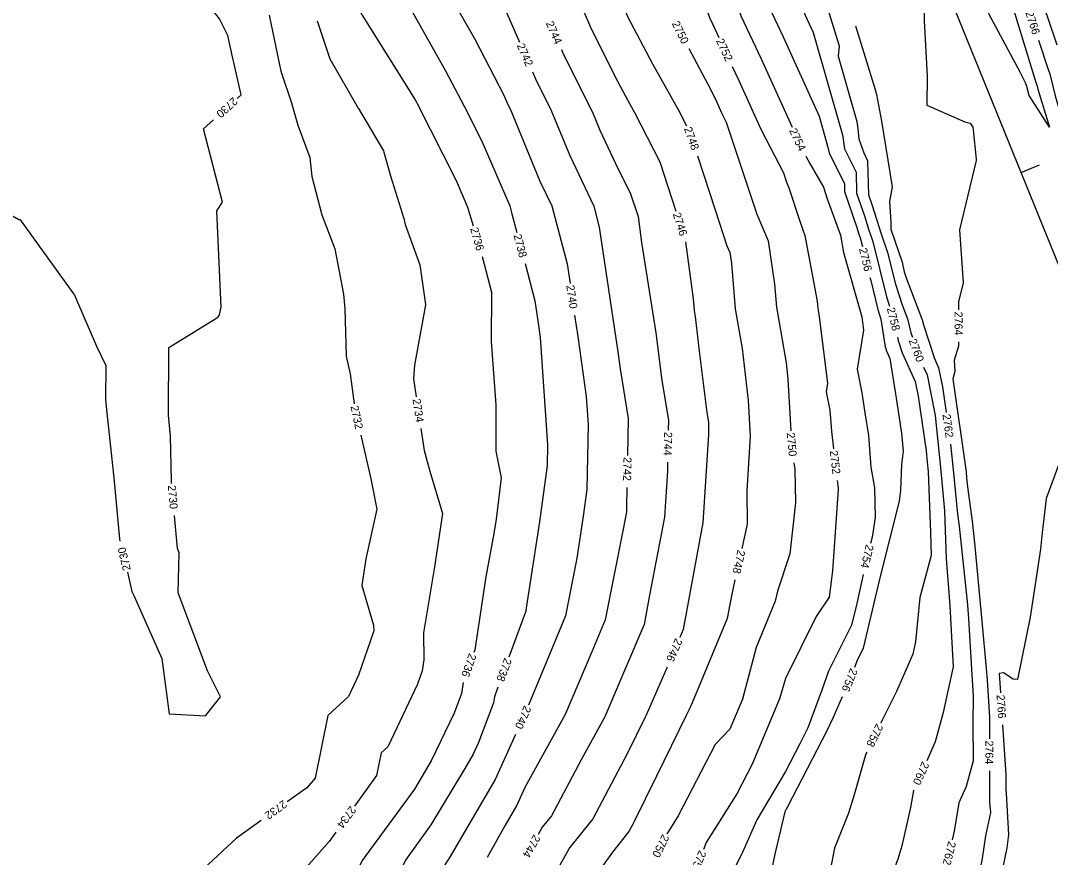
# Model space of a CAD drawing. Extents: x 1326424 to 1329294, y 1001359 to 1003823.
# Drawn here: x 1327991.3 to 1328248.6, y 1002477.9 to 1002687.1 of the extents above; entities that cross this region are included whole.
import ezdxf

# ---------------------------------------------------------------- set-up
doc = ezdxf.new("R2010")
doc.units = 0
for name, color, linetype in [('Prop RDY Alternate Text Yellow', 7, 'Continuous'), ('Prop Rem of Exist Asph Pvmt', 7, 'Continuous'), ('Prop SS Fill Line', 7, 'Continuous'), ('Scratch_Level_3', 7, 'Continuous')]:
    doc.layers.add(name, color=color, linetype=linetype)

msp = doc.modelspace()

# ---------------------------------------------------------------- linework, layer by layer
at = {"layer": 'Prop RDY Alternate Text Yellow'}
msp.add_line((1328073.66, 1003062.05), (1328254.1, 1002617.56), dxfattribs=at)
at = {"layer": 'Prop Rem of Exist Asph Pvmt'}
for points in [[(1328089.78, 1002713.03), (1328096.09, 1002698.14), (1328100.16, 1002690.63), (1328104.83, 1002682.41), (1328112.07, 1002668.46), (1328113.08, 1002666.12), (1328113.65, 1002664.98), (1328121.1, 1002646.94), (1328124.03, 1002640.73), (1328127.87, 1002626.26), (1328128.6, 1002621.38)], [(1328188.16, 1002703.79), (1328188.87, 1002701.14), (1328191.38, 1002695.22), (1328191.84, 1002693.74), (1328195.87, 1002680.76), (1328195.59, 1002678.15), (1328200.24, 1002661.87), (1328200.5, 1002660.12), (1328200.74, 1002657.47), (1328201.99, 1002654.05), (1328202.98, 1002652.04), (1328203.22, 1002643.48), (1328204.04, 1002641.07), (1328205.82, 1002635.37), (1328206.22, 1002634.25), (1328207.96, 1002629.1), (1328209.93, 1002621.15), (1328211.59, 1002616.03), (1328212.93, 1002612.5), (1328213.77, 1002609.05), (1328214.15, 1002607.9)], [(1328129.76, 1002613.46), (1328130.55, 1002608.12), (1328132.63, 1002593.1), (1328133.1, 1002586.12), (1328132.79, 1002569.84), (1328131.9, 1002563.18), (1328130.29, 1002552.67), (1328127.44, 1002538.3), (1328118.24, 1002515.97)], [(1328216.96, 1002600.42), (1328217.81, 1002598.55), (1328219.78, 1002588.78), (1328219.85, 1002588.34), (1328221.16, 1002575.35), (1328222.19, 1002564.5), (1328222.37, 1002559.72), (1328222.6, 1002552.6), (1328223.53, 1002540.78), (1328223.88, 1002534.64), (1328224.38, 1002525.55), (1328223.13, 1002519.86), (1328221.84, 1002514.12), (1328219.87, 1002506.74), (1328217.73, 1002501.99)], [(1328115, 1002508.65), (1328109.88, 1002497.34), (1328098.38, 1002477.7), (1328098.09, 1002477.19), (1328097.78, 1002476.69), (1328085.49, 1002456.36), (1328081.34, 1002446.53), (1328076.91, 1002436.36), (1328072.26, 1002421.62), (1328071.63, 1002419.02)], [(1328214.46, 1002494.69), (1328214.42, 1002494.6), (1328213.69, 1002490.34), (1328211.55, 1002480.8), (1328210.5, 1002477.41), (1328210.09, 1002476.39), (1328209.96, 1002475.75), (1328203.2, 1002469.13), (1328201.71, 1002459.43), (1328198.35, 1002441.71), (1328198.36, 1002441.68), (1328198.34, 1002441.64), (1328197.99, 1002440.77), (1328194.94, 1002433.24), (1328194.87, 1002432.95), (1328194.81, 1002432.1), (1328193.7, 1002420.89), (1328190.53, 1002411.21), (1328189.04, 1002408.1), (1328189.5, 1002405.5), (1328189.62, 1002404.46), (1328189.43, 1002400.15)]]:
    msp.add_lwpolyline(points, dxfattribs=at)
at = {"layer": 'Prop SS Fill Line'}
msp.add_line((1328241.3, 1002649.09), (1328245.94, 1002650.97), dxfattribs=at)
at = {"layer": 'Scratch_Level_3'}
for points in [[(1328080.12, 1002774.2), (1328081.58, 1002770.48), (1328082.26, 1002766.42), (1328083.71, 1002756.38), (1328084.7, 1002751.39), (1328086.49, 1002746.78), (1328087.65, 1002742.3), (1328089.21, 1002737.87), (1328090.81, 1002734.15), (1328090.83, 1002733.58), (1328095.51, 1002724.04), (1328100.07, 1002714.25), (1328103.48, 1002706.18), (1328111.68, 1002691.07), (1328112.13, 1002690.28), (1328112.83, 1002688.92), (1328116.01, 1002681.64)], [(1328218.56, 1002775.72), (1328221.28, 1002768.47), (1328223.52, 1002761.33), (1328226.69, 1002754.93), (1328229.01, 1002748.13), (1328230.87, 1002739.46), (1328231.07, 1002738.8), (1328234.26, 1002731.13), (1328236.8, 1002722.92), (1328240.94, 1002710.39), (1328244.64, 1002697.22), (1328247.92, 1002687.96), (1328250.21, 1002681.05)], [(1328124.78, 1002772.2), (1328125.03, 1002770.89), (1328130.67, 1002758.18), (1328130.76, 1002753.81), (1328132.82, 1002752.09), (1328132.85, 1002752.01), (1328136.84, 1002746.97), (1328137.67, 1002742.78), (1328144.77, 1002733.53), (1328147.36, 1002726.98), (1328152.65, 1002710.29), (1328154.21, 1002707.82), (1328156.81, 1002705.15), (1328158.89, 1002699.89), (1328163.51, 1002687.69), (1328163.57, 1002687.52), (1328163.67, 1002687.34), (1328165.77, 1002682.84)], [(1328045.44, 1002667.62), (1328046.41, 1002668.51), (1328044.57, 1002676.62), (1328044.43, 1002677.26), (1328043.06, 1002683.36), (1328041.03, 1002687.49), (1328032.58, 1002698.39), (1328032.6, 1002700.23), (1328031.92, 1002705.65), (1328026.93, 1002716.92), (1328025.07, 1002725.12), (1328025.02, 1002729.67), (1328023.32, 1002732.98), (1328025.08, 1002738.08), (1328024.2, 1002743.03), (1328024.03, 1002745.75), (1328024.3, 1002753.16), (1328024.24, 1002761.36)], [(1328145.76, 1002752.24), (1328146.37, 1002750.07), (1328149.14, 1002745.49), (1328153.09, 1002740.34), (1328153.83, 1002738.47), (1328161.92, 1002712.91), (1328162.2, 1002712.47), (1328162.66, 1002712), (1328166.99, 1002701.07), (1328169.55, 1002694.3), (1328171.31, 1002688.29), (1328176.33, 1002677.55), (1328184.09, 1002660.43)], [(1328114.39, 1002748.69), (1328116.61, 1002747.47), (1328121.98, 1002743), (1328122.1, 1002742.6), (1328122.77, 1002741.76), (1328126.72, 1002721.73), (1328128.13, 1002719.9), (1328133.06, 1002707.47), (1328134.32, 1002704.79), (1328135.78, 1002701.73), (1328139.57, 1002694.98), (1328141.54, 1002691.83), (1328142.93, 1002688.09), (1328149.25, 1002676.29), (1328155.73, 1002664.7), (1328157.75, 1002660.76)], [(1328114.77, 1002730.6), (1328115.33, 1002727.66), (1328116.07, 1002724.26), (1328119.65, 1002715.55), (1328121.67, 1002711.17), (1328126.92, 1002700.06), (1328131.86, 1002689.67), (1328133.73, 1002685.39), (1328139.78, 1002673.17), (1328143.05, 1002667.06), (1328144.71, 1002664.09), (1328151.02, 1002651.78), (1328155.06, 1002639.4)], [(1328060.69, 1002725.37), (1328062.98, 1002719.5), (1328064.91, 1002715.46), (1328074.27, 1002693.07), (1328076.63, 1002688.39), (1328089.92, 1002667.23), (1328090.23, 1002666.69), (1328090.39, 1002666.38), (1328100.14, 1002647.09), (1328103.02, 1002640.4), (1328104.42, 1002635.75)], [(1328072.62, 1002724.29), (1328076.89, 1002715.33), (1328081.55, 1002704.17), (1328088.63, 1002690.17), (1328088.8, 1002689.89), (1328097.53, 1002674.55), (1328102.14, 1002665.66), (1328106.57, 1002656.89), (1328113.54, 1002640.74), (1328113.63, 1002640.46), (1328114.07, 1002638.78), (1328115.31, 1002634.09)], [(1328168.13, 1002724.44), (1328174.13, 1002704.67), (1328175.09, 1002702.25), (1328175.51, 1002701.14), (1328179.04, 1002689.04), (1328181.86, 1002683), (1328190.84, 1002663.21), (1328193.15, 1002655.11), (1328193.32, 1002654.01), (1328196.15, 1002648.47), (1328197.17, 1002646.38), (1328197.23, 1002644.31), (1328200.27, 1002635.38), (1328200.73, 1002633.93), (1328201.14, 1002632.77), (1328201.66, 1002630.63)], [(1328237.47, 1002696.29), (1328237.64, 1002695.69), (1328244.73, 1002672.46), (1328245.25, 1002670.9), (1328245.32, 1002670.71), (1328245.49, 1002669.95), (1328248.4, 1002660.45), (1328243.34, 1002668.31), (1328242.76, 1002670.58), (1328242.38, 1002671.54), (1328241.07, 1002674.18), (1328232.61, 1002690.04), (1328230.79, 1002696.35), (1328229.91, 1002698), (1328223.13, 1002710.42), (1328221.28, 1002713.82), (1328220.49, 1002715.15), (1328220.24, 1002714.31)], [(1328179.69, 1002711.01), (1328180.37, 1002708.38), (1328182.11, 1002701.88), (1328185.76, 1002693.27), (1328186.78, 1002689.8), (1328187.4, 1002688.45), (1328189.39, 1002684.06), (1328196.69, 1002658.49), (1328197.22, 1002655), (1328197.45, 1002654.55), (1328200.07, 1002649.21), (1328200.23, 1002643.89), (1328202.16, 1002638.23), (1328203.27, 1002634.65), (1328204.1, 1002632.34), (1328204.37, 1002631.54), (1328207.72, 1002618.02), (1328208.46, 1002615.71)], [(1328218.76, 1002706.46), (1328216.79, 1002693.23), (1328217.06, 1002690.04), (1328217.12, 1002686.97), (1328217.85, 1002673.15), (1328217.78, 1002665.95), (1328227.26, 1002661.73), (1328228.62, 1002661.39), (1328229.24, 1002660.43), (1328229.35, 1002659.75), (1328230.13, 1002652.45), (1328230.12, 1002652.3), (1328230.08, 1002652.13), (1328225.93, 1002634.74), (1328226.86, 1002621.55), (1328225.68, 1002616.76), (1328225.69, 1002614.76)], [(1328053.43, 1002688.42), (1328056.34, 1002674.45), (1328059.11, 1002666.27), (1328059.13, 1002666.21), (1328060.57, 1002660.94), (1328063.55, 1002652.83), (1328064.09, 1002648.12), (1328066.57, 1002638.55), (1328069.84, 1002630), (1328072.02, 1002618.69), (1328072.32, 1002615.04), (1328072.67, 1002603.2), (1328073.66, 1002598.77), (1328074.68, 1002591.26)], [(1328065.41, 1002687.02), (1328068.6, 1002677.54), (1328075.69, 1002665.21), (1328075.73, 1002665.09), (1328082, 1002654.47), (1328082.1, 1002654.14), (1328083.73, 1002648.23), (1328087.11, 1002637.63), (1328087.39, 1002636.12), (1328091.09, 1002625.99), (1328092.46, 1002616.09), (1328092.45, 1002616), (1328089.73, 1002600.94), (1328089.48, 1002597.52), (1328090.17, 1002592.99)], [(1328199.95, 1002685.74), (1328204.81, 1002670.1), (1328205.19, 1002668.61), (1328206.41, 1002661.9), (1328209.13, 1002645.48), (1328208.45, 1002641.88), (1328208.78, 1002636.64), (1328208.78, 1002636.61), (1328208.76, 1002634.91), (1328211.56, 1002626.65), (1328212.14, 1002624.29), (1328212.64, 1002622.76), (1328216.62, 1002612.27), (1328216.92, 1002611.03), (1328219.67, 1002602.6), (1328220.72, 1002600.28), (1328221.69, 1002595.51), (1328222.59, 1002589.14)], [(1328245.68, 1002682.16), (1328248.02, 1002675.1), (1328248.5, 1002673.75), (1328249.8, 1002668.22), (1328251.07, 1002664.04), (1328254.35, 1002656.84), (1328260.86, 1002639.65), (1328261.98, 1002634.05), (1328264.08, 1002630.13), (1328268.84, 1002621.9), (1328270.93, 1002618.14), (1328271.04, 1002617.67), (1328271.02, 1002617.17), (1328270.8, 1002616.04), (1328269.46, 1002602.89), (1328270.17, 1002600.81), (1328270.34, 1002597.17), (1328269.47, 1002594.53), (1328270.66, 1002592.37), (1328270.42, 1002589.99), (1328269.28, 1002588.37)], [(1328126.46, 1002679.86), (1328126.85, 1002678.96), (1328134.19, 1002664.15), (1328136.02, 1002659.7), (1328140.65, 1002649.91), (1328143.66, 1002644.04), (1328145.6, 1002638.09), (1328146.45, 1002631.63), (1328150.05, 1002609.02), (1328151.56, 1002597.06), (1328153.2, 1002587.17), (1328153.15, 1002584.67)], [(1328158.32, 1002680.06), (1328163.73, 1002669.91), (1328165.25, 1002666.64), (1328166.44, 1002664.02), (1328167.64, 1002661.69), (1328175.26, 1002638.72), (1328178.14, 1002632.03), (1328179.69, 1002621.18), (1328180.19, 1002615.41), (1328182.59, 1002601.48), (1328183.05, 1002597.42), (1328183.81, 1002584.5)], [(1328119.2, 1002674.3), (1328119.97, 1002672.54), (1328123.92, 1002664.56), (1328128.56, 1002653.32), (1328134.52, 1002640.7), (1328135.91, 1002635.46), (1328140.53, 1002604.23), (1328141.11, 1002600.03), (1328143.17, 1002587.62), (1328142.99, 1002578.38)], [(1328169.16, 1002675.59), (1328170.79, 1002672.09), (1328176.32, 1002659.89), (1328181.93, 1002649.02), (1328182.7, 1002646.71), (1328183.31, 1002645.29), (1328186.1, 1002636.66), (1328187.32, 1002633.32), (1328190.32, 1002616.92), (1328190.45, 1002616.01), (1328190.47, 1002615.8), (1328190.56, 1002615.27), (1328190.82, 1002612.99), (1328192.96, 1002596.42), (1328192.62, 1002594.26), (1328193.52, 1002589.65), (1328193.91, 1002584.47), (1328194.45, 1002580.02)], [(1328029.05, 1002571.36), (1328029, 1002571.99), (1328028.77, 1002583.16), (1328028.3, 1002588.43), (1328028.38, 1002605.31), (1328040.14, 1002612.56), (1328040.79, 1002613.08), (1328041.01, 1002613.52), (1328041.44, 1002615.47), (1328040.32, 1002639.52), (1328041.74, 1002641.71), (1328037.05, 1002659.97), (1328039.53, 1002662.23)], [(1328160.44, 1002653.24), (1328164.84, 1002639.73), (1328167.83, 1002630.73), (1328168.55, 1002629.06), (1328168.93, 1002626.35), (1328169.91, 1002615.02), (1328171.61, 1002605.13), (1328173.13, 1002592.13), (1328173.66, 1002583.22), (1328172.79, 1002569.5), (1328172.91, 1002561.16), (1328171.55, 1002555.07)], [(1328187.52, 1002653.21), (1328188.5, 1002651.31), (1328191.92, 1002645.44), (1328192.88, 1002642.48), (1328196.2, 1002633.4), (1328196.98, 1002629.09), (1328201.49, 1002612.98), (1328201.91, 1002609.68), (1328200.37, 1002599.93), (1328201.53, 1002594.03), (1328202.31, 1002589.02), (1328203.16, 1002583.35), (1328203.81, 1002575.43), (1328204.71, 1002570.29), (1328204.83, 1002562.88), (1328204.07, 1002557.9), (1328203.69, 1002556.39)], [(1327979.93, 1002644.44), (1327989.31, 1002638.24), (1327990.88, 1002637.36), (1327991.16, 1002637.37), (1327991.46, 1002636.93), (1328004.81, 1002618.42), (1328010.28, 1002605.68), (1328012.59, 1002600.82), (1328012.55, 1002592.38), (1328012.79, 1002589.75), (1328014.63, 1002572.78), (1328016, 1002557.55), (1328016.15, 1002556.93)], [(1328157.49, 1002631.78), (1328159.38, 1002617.48), (1328159.63, 1002614.63), (1328159.89, 1002613.09), (1328160.9, 1002604.44), (1328162.83, 1002589.14), (1328163.23, 1002586.72), (1328163.17, 1002583.59), (1328161.79, 1002561.54), (1328160.84, 1002556.61), (1328156.89, 1002534.83), (1328156.02, 1002532.82)], [(1328106.63, 1002628.06), (1328108.97, 1002619.15), (1328108.89, 1002606.85), (1328110.08, 1002591.01), (1328110.08, 1002579.45), (1328111.43, 1002572.8), (1328110.15, 1002562.4), (1328109.53, 1002558.84), (1328107.54, 1002548.03), (1328104.78, 1002529.76), (1328104.54, 1002529.11)], [(1328117.36, 1002626.35), (1328119.84, 1002617.05), (1328120.58, 1002612.01), (1328121.15, 1002607.85), (1328122.96, 1002581.04), (1328122.86, 1002575.83), (1328121, 1002561.81), (1328117.6, 1002539.69), (1328117.53, 1002539.35), (1328117.29, 1002538.78), (1328113.33, 1002527.97)], [(1328203.54, 1002622.85), (1328203.73, 1002622.06), (1328205.5, 1002614.88), (1328206.29, 1002612.46), (1328207.39, 1002605.48), (1328207.48, 1002605.09), (1328207.61, 1002604.72), (1328208.55, 1002602.63), (1328209.94, 1002593.78), (1328211.41, 1002583.95), (1328211.83, 1002579.44), (1328211.43, 1002576.13), (1328211.22, 1002569.61), (1328210.81, 1002566.96), (1328206, 1002547.74), (1328205.3, 1002544.58), (1328201.87, 1002530.19), (1328200.24, 1002526.94), (1328199.68, 1002525.39)], [(1328210.41, 1002607.97), (1328210.63, 1002607.07), (1328211.63, 1002604.01), (1328214.89, 1002596.82), (1328215.64, 1002593.15), (1328217.59, 1002579.53), (1328217.88, 1002576.66), (1328218.1, 1002574.36), (1328218.69, 1002559.08), (1328218.87, 1002553.34), (1328215.98, 1002542.85), (1328214.97, 1002531.78), (1328214.54, 1002529.82), (1328214.28, 1002528.69), (1328210.19, 1002519.33), (1328206.47, 1002511.82), (1328206.27, 1002511.4)], [(1328225.7, 1002606.76), (1328225.7, 1002605.69), (1328224.56, 1002602.17), (1328224.76, 1002599.35), (1328224.25, 1002597.55), (1328227.56, 1002574.28), (1328227.71, 1002572.73), (1328227.92, 1002570.52), (1328229.09, 1002561.92), (1328229.66, 1002556.51), (1328231.56, 1002536), (1328232.56, 1002525.13), (1328232.83, 1002522.24), (1328233.46, 1002512.85), (1328233.41, 1002507.54)], [(1328263.19, 1002585.46), (1328262.46, 1002586.07), (1328258.77, 1002585.65), (1328257.95, 1002585.2), (1328255.16, 1002594.9), (1328255.08, 1002593.71), (1328254.18, 1002585.43), (1328247.58, 1002567.6), (1328246.75, 1002560.41), (1328246.59, 1002559.08), (1328246.17, 1002554.92), (1328243.57, 1002537.96), (1328240.38, 1002522.34), (1328239.37, 1002522.44), (1328236.9, 1002524.05), (1328235.83, 1002523.85), (1328236.16, 1002518.99)], [(1328076.35, 1002583.44), (1328078.87, 1002572.48), (1328080.32, 1002564.96), (1328077.56, 1002552.49), (1328076.58, 1002545.86), (1328079.52, 1002535.95), (1328079.55, 1002534.4), (1328079.52, 1002534.24), (1328075.79, 1002523.4), (1328073.27, 1002518.11), (1328068.05, 1002513.36), (1328064.9, 1002497.73), (1328062.84, 1002495.29), (1328057.92, 1002491.77)], [(1328091.36, 1002585.08), (1328092.12, 1002579.61), (1328093.55, 1002574.42), (1328096.74, 1002563.85), (1328095.66, 1002556.59), (1328094.78, 1002550.52), (1328091.96, 1002533.99), (1328092.08, 1002527.29), (1328091.64, 1002524.54), (1328090.49, 1002521.18), (1328083.04, 1002505.53), (1328081.42, 1002504.06), (1328080.26, 1002498.32), (1328074.79, 1002490.69)], [(1328223.71, 1002581.21), (1328224.44, 1002574.04), (1328225.41, 1002563.72), (1328225.83, 1002560.68), (1328227.9, 1002541.04), (1328228.01, 1002539.78), (1328228.21, 1002537.62), (1328228.93, 1002524.97), (1328229.31, 1002518.19), (1328229.24, 1002511.46), (1328229.31, 1002501.99), (1328227.59, 1002495.57), (1328225.78, 1002491.55), (1328224.57, 1002484.45), (1328224.12, 1002482.24)], [(1328153, 1002576.67), (1328152.96, 1002574.44), (1328152.23, 1002562.91), (1328148.5, 1002543.43), (1328147.17, 1002536.09), (1328142.21, 1002524.57), (1328137.31, 1002513.03), (1328131.37, 1002502.31), (1328123.95, 1002488.26), (1328121.67, 1002485.42), (1328120.66, 1002483.63)], [(1328184.56, 1002576.54), (1328184.76, 1002574.97), (1328184.96, 1002566.52), (1328183.57, 1002553.8), (1328180.44, 1002544.43), (1328179.86, 1002541.91), (1328175.13, 1002530.35), (1328171.73, 1002517.41), (1328168.54, 1002509.95), (1328164.88, 1002506.1), (1328155.64, 1002488.29), (1328153.91, 1002485.42), (1328152.83, 1002483.75)], [(1328142.84, 1002570.38), (1328142.74, 1002565.29), (1328142.68, 1002564.29), (1328141.85, 1002559.95), (1328137.35, 1002537.25), (1328134.07, 1002529.28), (1328127.39, 1002513.58), (1328117.33, 1002495.4), (1328115.33, 1002490.98), (1328112.3, 1002485.81), (1328107.93, 1002477.89)], [(1328195.4, 1002572.08), (1328195.62, 1002570.26), (1328195.63, 1002570.2), (1328195.59, 1002569.82), (1328194.2, 1002549.51), (1328193.37, 1002542.95), (1328190.08, 1002538.11), (1328182.45, 1002522.6), (1328180.97, 1002517.55), (1328174.15, 1002501.17), (1328170.29, 1002493.74), (1328162.65, 1002481.64), (1328161.92, 1002479.85)], [(1328018, 1002549.15), (1328019.15, 1002544.36), (1328019.58, 1002543.39), (1328026.61, 1002527.63), (1328028.41, 1002513.76), (1328037.52, 1002513.28), (1328041.29, 1002518.06), (1328038.03, 1002524.54), (1328030.68, 1002543.99), (1328030.91, 1002553.99), (1328030.52, 1002555.1), (1328029.77, 1002563.39)], [(1328169.82, 1002547.26), (1328168.85, 1002542.88), (1328167.91, 1002537.58), (1328159.1, 1002516.56), (1328158.37, 1002514.88), (1328157.62, 1002513.34), (1328150.21, 1002498.19), (1328144.67, 1002486.85), (1328144.58, 1002486.71), (1328144.33, 1002486.19), (1328143.32, 1002484.34), (1328139.2, 1002479.16), (1328130.94, 1002467.7), (1328130.16, 1002466.33), (1328126.02, 1002458.19)], [(1328201.86, 1002548.61), (1328200.26, 1002541.36), (1328198.97, 1002535.96), (1328193.17, 1002524.4), (1328191.57, 1002519.96), (1328187.99, 1002510.26), (1328186.07, 1002506.26), (1328182.47, 1002499.32), (1328175.29, 1002487.3), (1328171.52, 1002478.8), (1328168.59, 1002473.12), (1328163.03, 1002460.15), (1328161.96, 1002457.37)], [(1328152.85, 1002525.48), (1328147.64, 1002513.47), (1328147.38, 1002512.95), (1328142.9, 1002503.77), (1328134.32, 1002487.55), (1328128.5, 1002480.3), (1328124.46, 1002473.13), (1328119.53, 1002464.51), (1328117.35, 1002460.22), (1328111.34, 1002448.11), (1328108.2, 1002442.13), (1328105.95, 1002437.78), (1328105.8, 1002437.49)], [(1328101.87, 1002521.58), (1328101.49, 1002518.88), (1328099.63, 1002513.96), (1328093.94, 1002502.01), (1328089.71, 1002494.95), (1328076.67, 1002477.07), (1328071.68, 1002466.9), (1328065.96, 1002457.72), (1328060.89, 1002447.21), (1328056.67, 1002433.23)], [(1328110.58, 1002520.46), (1328109.7, 1002518.05), (1328109.48, 1002516.5), (1328105.75, 1002506.63), (1328104.43, 1002503.7), (1328102.3, 1002500.07), (1328093.85, 1002486), (1328087.46, 1002477.23), (1328082.64, 1002467.4), (1328077.69, 1002459.22), (1328070.4, 1002441.93), (1328069.22, 1002439.21), (1328066.69, 1002431.21)], [(1328196.64, 1002517.99), (1328194.31, 1002512.73), (1328192.78, 1002509.52), (1328182.92, 1002490.49), (1328182.7, 1002490.12), (1328182.31, 1002489.24), (1328179.72, 1002478.38), (1328178.88, 1002474.23), (1328175.48, 1002459.18), (1328174.39, 1002453.82), (1328171.45, 1002448.95), (1328169.98, 1002437.84), (1328167.38, 1002431.17), (1328164.17, 1002424.38)], [(1328236.69, 1002511.01), (1328237.53, 1002498.58), (1328237.51, 1002497.12), (1328237.53, 1002494.96), (1328237.61, 1002493.83), (1328238.21, 1002483.6), (1328237.74, 1002480.29), (1328235.1, 1002467.4), (1328234.2, 1002463.61), (1328232.89, 1002457.31), (1328230.89, 1002447.89), (1328227.96, 1002440.79), (1328225.2, 1002435.82), (1328224.78, 1002435.36), (1328224.56, 1002433.14), (1328223.6, 1002431.24), (1328221.73, 1002426.63), (1328217.21, 1002417.02), (1328216.75, 1002415.44), (1328216.63, 1002414.96)], [(1328202.74, 1002504.22), (1328202.51, 1002503.76), (1328199.64, 1002493.51), (1328198.22, 1002488.95), (1328194.71, 1002480.2), (1328193.6, 1002474.73), (1328191.23, 1002472.4), (1328190.71, 1002468.99), (1328189.51, 1002462.72), (1328185.65, 1002443.67), (1328184.46, 1002440.72), (1328182.47, 1002432.78), (1328181.95, 1002425.88), (1328176.03, 1002413.47), (1328175.34, 1002412.03), (1328175.37, 1002411.84), (1328175.68, 1002409.22)], [(1328233.41, 1002499.54), (1328233.46, 1002491.68), (1328233.65, 1002489.13), (1328232.39, 1002483.29), (1328231.57, 1002477.58), (1328230.65, 1002473.11), (1328230.09, 1002470.73), (1328227.97, 1002461.64), (1328226.58, 1002455.11), (1328223.32, 1002447.22), (1328219.99, 1002439.6), (1328218.52, 1002436.71), (1328211.97, 1002420.56), (1328211.26, 1002419.04), (1328210.66, 1002416.97), (1328208.94, 1002412.6), (1328207.22, 1002408.96), (1328207.21, 1002408.45), (1328206.93, 1002404.23)], [(1328051.41, 1002487.11), (1328045.27, 1002482.72), (1328037.03, 1002475.04), (1328031.38, 1002459.54), (1328028.28, 1002455.31), (1328027.64, 1002451.52), (1328026.83, 1002448.63), (1328021.91, 1002431.16), (1328014.18, 1002418.82), (1328012.77, 1002418.67), (1328012.16, 1002417.03), (1327996.91, 1002410.86), (1327996.75, 1002410.64)], [(1328070.12, 1002484.19), (1328068.44, 1002481.84), (1328060.84, 1002473.24), (1328051.89, 1002459.44), (1328048.6, 1002447.07), (1328046.12, 1002439.08), (1328044.61, 1002419.25), (1328044.18, 1002415.57), (1328042.43, 1002397.32), (1328042.19, 1002395.26), (1328042.51, 1002391.25)]]:
    msp.add_lwpolyline(points, dxfattribs=at)

# ---------------------------------------------------------------- texts
at = {"layer": 'Prop Rem of Exist Asph Pvmt'}
for s, rotation, p in [('2740', 278.4082, (1328127.67, 1002620.82)), ('2760', 290.5709, (1328213.2, 1002607.09)), ('2740', 246.1307, (1328117.18, 1002515.98)), ('2760', 245.8168, (1328216.64, 1002502))]:
    msp.add_text(s, height=2, rotation=rotation, dxfattribs=at).set_placement(p)
at = {"layer": 'Scratch_Level_3'}
for s, rotation, p in [('2766', 287.7625, (1328242.37, 1002689.05)), ('2744', 293.5259, (1328122.51, 1002686.42)), ('2750', 295.9371, (1328153.98, 1002686.37)), ('2742', 293.5259, (1328115.26, 1002680.85)), ('2752', 295.0314, (1328165.04, 1002682.04)), ('2730', 222.3902, (1328044.43, 1002668.06)), ('2748', 289.6368, (1328157.05, 1002660.08)), ('2754', 295.4354, (1328183.3, 1002659.59)), ('2746', 287.6747, (1328154.26, 1002638.71)), ('2736', 286.034, (1328103.64, 1002635.06)), ('2738', 284.8669, (1328114.46, 1002633.4)), ('2756', 283.577, (1328200.79, 1002629.99)), ('2758', 284.1083, (1328207.75, 1002615.11)), ('2764', 270.0939, (1328224.69, 1002614.32)), ('2732', 282.0595, (1328073.74, 1002590.6)), ('2734', 278.5525, (1328089.25, 1002592.4)), ('2762', 278.0517, (1328221.66, 1002588.57)), ('2744', 268.9073, (1328152.14, 1002584.27)), ('2750', 275.3741, (1328182.75, 1002583.99)), ('2742', 268.9073, (1328141.98, 1002577.98)), ('2752', 276.8532, (1328193.5, 1002579.49)), ('2730', 275.1302, (1328028.1, 1002570.83)), ('2730', 103.4292, (1328018.87, 1002549.82)), ('2748', 257.4801, (1328170.49, 1002554.88)), ('2754', 256.7621, (1328202.57, 1002556.23)), ('2746', 246.6378, (1328154.95, 1002532.83)), ('2736', 250.4966, (1328103.4, 1002529.03)), ('2738', 249.8835, (1328112.24, 1002527.89)), ('2756', 247.6965, (1328198.7, 1002525.34)), ('2766', 273.8311, (1328235.19, 1002518.49)), ('2758', 243.8532, (1328205.18, 1002511.47)), ('2764', 270.0125, (1328232.38, 1002507.11)), ('2732', 215.5712, (1328056.97, 1002492.32)), ('2734', 234.3444, (1328073.71, 1002490.91)), ('2744', 240.5541, (1328119.58, 1002483.76)), ('2750', 243.6768, (1328151.71, 1002483.84)), ('2762', 256.2141, (1328223.15, 1002482.03)), ('2752', 247.1149, (1328160.9, 1002479.83))]:
    msp.add_text(s, height=2, rotation=rotation, dxfattribs=at).set_placement(p)

doc.saveas('drawing.dxf')
